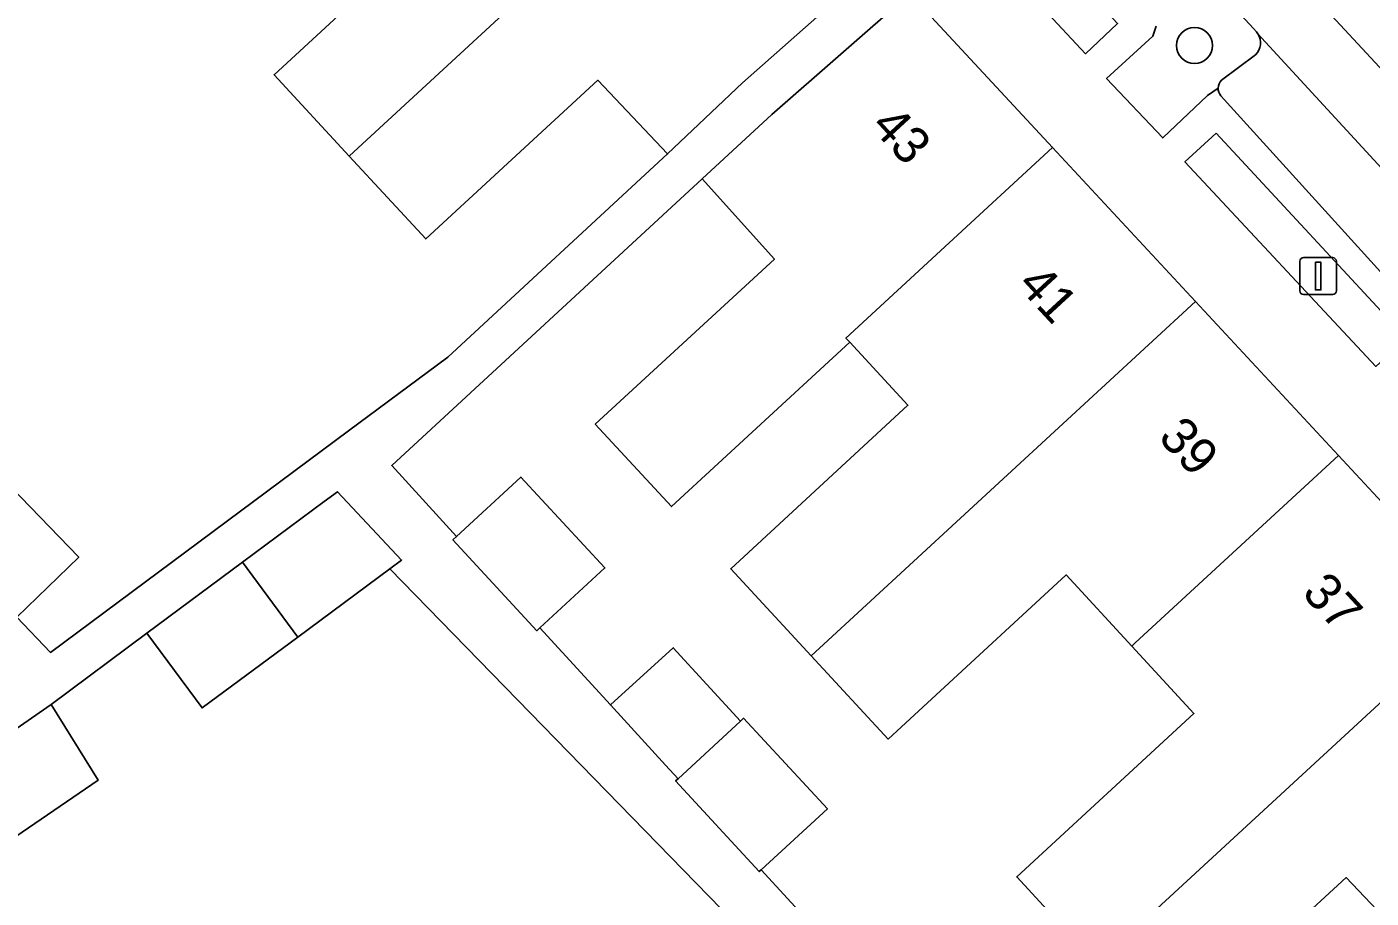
# Model space of a CAD drawing. Extents: x 159716 to 160783, y 383290 to 384031.
# Drawn here: x 160412.95 to 160449.4, y 383595.01 to 383618.65 of the extents above; entities that cross this region are included whole.
import ezdxf

# ---------------------------------------------------------------- set-up
doc = ezdxf.new("R2010")
doc.units = 0
for name, color, linetype in [('IMGEO_Boom', 7, 'Continuous'), ('IMGEO_Erf', 7, 'Continuous'), ('IMGEO_Groenvoorziening', 7, 'Continuous'), ('IMGEO_Lichtmast', 7, 'Continuous'), ('IMGEO_Pand', 7, 'Continuous'), ('IMGEO_Pand_nummerreeks', 7, 'Continuous'), ('IMGEO_Parkeervlak_open', 7, 'Continuous'), ('IMGEO_Rijbaan_lokaal_gesloten', 7, 'Continuous'), ('IMGEO_Rijbaan_lokaal_open', 7, 'Continuous'), ('IMGEO_Voetpad_open', 7, 'Continuous')]:
    doc.layers.add(name, color=color, linetype=linetype)

msp = doc.modelspace()

# ---------------------------------------------------------------- linework, layer by layer
at = {"layer": 'IMGEO_Boom'}
msp.add_circle((160444.613, 383618.147), 0.489, dxfattribs=at)
at = {"layer": 'IMGEO_Erf'}
for points in [[(160412.256, 383606.439), (160414.358, 383604.26), (160412.676, 383602.637), (160413.594, 383601.677), (160421.674, 383607.687), (160424.363, 383609.687), (160430.323, 383615.205), (160428.435, 383617.205), (160423.767, 383612.896), (160421.69, 383615.146), (160419.653, 383617.352), (160424.282, 383621.625), (160422.483, 383623.574), (160420.737, 383625.466), (160416.127, 383621.211), (160414.037, 383623.475), (160412.055, 383625.623), (160416.674, 383629.886), (160414.819, 383631.895), (160413.12, 383633.736), (160408.508, 383629.478)], [(160440.519, 383594.802), (160439.794, 383595.587), (160444.598, 383600.021), (160442.91, 383601.849), (160441.129, 383603.779), (160436.304, 383599.326), (160434.22, 383601.584), (160432.037, 383603.949), (160436.842, 383608.384), (160435.262, 383610.096), (160430.427, 383605.634), (160428.364, 383607.869), (160433.219, 383612.35), (160431.262, 383614.527), (160422.843, 383606.746), (160424.602, 383604.821), (160426.349, 383606.434), (160428.624, 383603.97), (160426.864, 383602.346), (160428.776, 383600.253), (160430.476, 383601.806), (160432.299, 383599.812), (160432.387, 383599.893), (160434.656, 383597.434), (160432.866, 383595.782), (160436.216, 383592.123)], [(160411.784, 383580.396), (160414.301, 383582.347), (160418.229, 383577.282), (160419.676, 383578.404), (160421.151, 383579.547), (160417.211, 383584.628), (160419.701, 383586.558), (160422.209, 383588.503), (160426.134, 383583.438), (160427.591, 383584.567), (160429.122, 383585.755), (160425.189, 383590.828), (160427.622, 383592.715), (160430.084, 383594.625), (160433.988, 383589.59), (160435.593, 383590.804), (160422.791, 383603.945), (160420.296, 383602.093), (160417.704, 383600.17), (160416.206, 383602.202), (160413.613, 383600.264), (160414.882, 383598.21), (160412.127, 383596.328)], [(160450.731, 383593.456), (160448.722, 383595.569), (160443.909, 383591.127)]]:
    msp.add_lwpolyline(points, dxfattribs=at)
at = {"layer": 'IMGEO_Groenvoorziening'}
for points in [[(160437.238, 383624.444), (160436.346, 383623.624), (160441.658, 383617.922), (160442.526, 383618.74)], [(160445.202, 383615.77), (160444.35, 383614.989), (160449.531, 383609.44), (160450.36, 383610.199)]]:
    msp.add_lwpolyline(points, close=True, dxfattribs=at)
for points in [[(160446.333, 383618.467), (160446.294, 383618.52), (160446.214, 383618.606), (160445.753, 383619.101), (160445.392, 383619.488), (160445.286, 383619.599)], [(160443.569, 383618.667), (160443.485, 383618.403), (160442.229, 383617.255), (160443.751, 383615.637), (160444.965, 383616.793), (160445.255, 383616.992)], [(160445.347, 383617.201), (160446.266, 383617.891)]]:
    msp.add_lwpolyline(points, dxfattribs=at)
for centre, radius, start, end in [((160445.937, 383618.221), 0.466, 314.8788, 31.8516), ((160445.566, 383616.98), 0.311, 134.6904, 177.7923)]:
    msp.add_arc(centre, radius, start, end, dxfattribs=at)
at = {"layer": 'IMGEO_Lichtmast'}
for p, q in [((160447.47, 383611.49), (160447.47, 383612.29)), ((160447.47, 383612.29), (160447.47, 383611.49)), ((160447.57, 383612.39), (160448.36, 383612.39)), ((160448.36, 383612.39), (160447.57, 383612.39)), ((160448.46, 383612.29), (160448.46, 383611.49)), ((160448.46, 383611.49), (160448.46, 383612.29)), ((160448.36, 383611.39), (160447.57, 383611.39)), ((160447.57, 383611.39), (160448.36, 383611.39))]:
    msp.add_line(p, q, dxfattribs=at)
msp.add_lwpolyline([(160447.89, 383612.265), (160448.04, 383612.265), (160448.04, 383611.515), (160447.89, 383611.515), (160447.89, 383612.265)], dxfattribs=at)
for centre, start, end in [((160447.57, 383612.29), 90, 180), ((160447.57, 383612.29), 90, 180), ((160448.36, 383612.29), 0, 90), ((160448.36, 383612.29), 360, 90), ((160447.57, 383611.49), 180, 270), ((160447.57, 383611.49), 180, 270), ((160448.36, 383611.49), 270, 0), ((160448.36, 383611.49), 270, 0)]:
    msp.add_arc(centre, 0.1, start, end, dxfattribs=at)
at = {"layer": 'IMGEO_Pand'}
for points in [[(160432.084, 383624.739), (160428.236, 383628.884), (160422.679, 383623.755), (160422.483, 383623.574), (160424.282, 383621.625), (160419.653, 383617.352), (160421.69, 383615.146), (160421.813, 383615.259)], [(160436.079, 383620.435), (160432.084, 383624.739), (160421.813, 383615.259), (160421.69, 383615.146), (160423.767, 383612.896), (160428.435, 383617.205), (160430.323, 383615.205), (160432.354, 383617.13)], [(160440.764, 383615.382), (160436.893, 383619.556), (160433.15, 383616.272), (160431.262, 383614.527), (160433.219, 383612.35), (160428.364, 383607.869), (160430.427, 383605.634), (160435.262, 383610.096), (160435.159, 383610.208)], [(160444.64, 383611.203), (160440.764, 383615.382), (160435.159, 383610.208), (160435.262, 383610.096), (160436.842, 383608.384), (160432.037, 383603.949), (160434.22, 383601.584), (160434.447, 383601.794)], [(160448.515, 383607.023), (160444.64, 383611.203), (160434.447, 383601.794), (160434.22, 383601.584), (160436.304, 383599.326), (160441.129, 383603.779), (160442.91, 383601.849), (160443.002, 383601.934)], [(160452.391, 383602.844), (160448.515, 383607.023), (160443.002, 383601.934), (160442.91, 383601.849), (160444.598, 383600.021), (160439.794, 383595.587), (160440.519, 383594.802), (160441.972, 383593.226)], [(160412.256, 383606.439), (160410.548, 383604.864), (160410.498, 383604.817), (160412.638, 383602.6), (160412.676, 383602.637), (160414.358, 383604.26)], [(160424.602, 383604.821), (160424.504, 383604.731), (160426.778, 383602.267), (160426.864, 383602.346), (160428.624, 383603.97), (160426.349, 383606.434)], [(160421.014, 383605.769), (160418.798, 383604.125), (160420.296, 383602.093), (160422.791, 383603.945), (160423.113, 383604.184), (160421.373, 383606.036)], [(160420.296, 383602.093), (160418.798, 383604.125), (160416.206, 383602.202), (160417.704, 383600.17)], [(160456.328, 383598.598), (160452.391, 383602.844), (160441.972, 383593.226), (160443.909, 383591.127), (160448.722, 383595.569), (160450.731, 383593.456), (160452.802, 383595.359)], [(160430.476, 383601.806), (160428.776, 383600.253), (160430.271, 383598.617), (160430.607, 383598.25), (160432.299, 383599.812)], [(160410.661, 383598.218), (160412.127, 383596.328), (160414.882, 383598.21), (160413.613, 383600.264)], [(160432.299, 383599.812), (160430.607, 383598.25), (160430.542, 383598.19), (160432.811, 383595.731), (160432.866, 383595.782), (160434.656, 383597.434), (160432.387, 383599.893)]]:
    msp.add_lwpolyline(points, close=True, dxfattribs=at)
at = {"layer": 'IMGEO_Parkeervlak_open'}
for points in [[(160459.018, 383604.673), (160446.333, 383618.467)], [(160446.266, 383617.891), (160445.347, 383617.201)], [(160445.327, 383616.78), (160457.086, 383603.81)]]:
    msp.add_lwpolyline(points, dxfattribs=at)
for centre, radius, start, end in [((160445.937, 383618.221), 0.466, 314.8788, 31.8516), ((160445.566, 383616.98), 0.311, 134.6904, 177.7923), ((160445.561, 383616.978), 0.306, 177.3228, 220.1945)]:
    msp.add_arc(centre, radius, start, end, dxfattribs=at)
at = {"layer": 'IMGEO_Rijbaan_lokaal_gesloten'}
msp.add_lwpolyline([(160428.501, 383637.667), (160431.144, 383634.815), (160431.472, 383634.461), (160432.462, 383633.429), (160432.527, 383633.339), (160445.286, 383619.599), (160445.392, 383619.488), (160445.753, 383619.101), (160446.214, 383618.606), (160446.294, 383618.52), (160446.333, 383618.467), (160459.018, 383604.673), (160459.094, 383604.601), (160460.412, 383605.803), (160451.956, 383615.047), (160433.35, 383635.117)], dxfattribs=at)
at = {"layer": 'IMGEO_Rijbaan_lokaal_open'}
msp.add_lwpolyline([(160430.561, 383638.144), (160433.35, 383635.117), (160451.956, 383615.047), (160460.412, 383605.803), (160459.094, 383604.601), (160459.348, 383604.307), (160464.132, 383608.674), (160463.857, 383608.975), (160462.488, 383607.758), (160454.707, 383616.185), (160444.209, 383627.615), (160437.436, 383634.886), (160423.641, 383649.415), (160423.767, 383649.538), (160424.907, 383650.657)], dxfattribs=at)
at = {"layer": 'IMGEO_Voetpad_open'}
for points in [[(160409.048, 383648.938), (160410.515, 383647.343), (160412.772, 383645.544), (160416.693, 383641.32), (160420.54, 383637.175), (160424.389, 383633.03), (160428.236, 383628.884), (160432.084, 383624.739), (160436.079, 383620.435), (160436.893, 383619.556), (160440.764, 383615.382), (160444.64, 383611.203), (160448.515, 383607.023), (160452.391, 383602.844), (160456.328, 383598.598), (160458.067, 383600.195), (160456.072, 383602.378), (160457.215, 383603.452), (160457.285, 383603.724)], [(160436.216, 383592.123), (160432.866, 383595.782), (160432.811, 383595.731), (160430.542, 383598.19), (160430.607, 383598.25), (160430.271, 383598.617), (160428.776, 383600.253), (160426.864, 383602.346), (160426.778, 383602.267), (160424.504, 383604.731), (160424.602, 383604.821), (160422.843, 383606.746), (160431.262, 383614.527), (160433.15, 383616.272), (160436.893, 383619.556), (160436.079, 383620.435), (160432.354, 383617.13), (160430.323, 383615.205), (160424.363, 383609.687), (160421.674, 383607.687), (160413.594, 383601.677), (160412.676, 383602.637)], [(160445.255, 383616.992), (160444.965, 383616.793), (160443.751, 383615.637), (160442.229, 383617.255), (160443.485, 383618.403), (160443.569, 383618.667)], [(160457.086, 383603.81), (160445.327, 383616.78)], [(160410.661, 383598.218), (160413.613, 383600.264), (160416.206, 383602.202), (160418.798, 383604.125), (160421.014, 383605.769), (160421.373, 383606.036), (160423.113, 383604.184), (160422.791, 383603.945), (160435.593, 383590.804)]]:
    msp.add_lwpolyline(points, dxfattribs=at)
for points in [[(160437.238, 383624.444), (160442.526, 383618.74), (160441.658, 383617.922), (160436.346, 383623.624)], [(160445.202, 383615.77), (160450.36, 383610.199), (160449.531, 383609.44), (160444.35, 383614.989)]]:
    msp.add_lwpolyline(points, close=True, dxfattribs=at)
msp.add_arc((160445.561, 383616.978), 0.306, 177.3228, 220.1945, dxfattribs=at)

# ---------------------------------------------------------------- texts
at = {"layer": 'IMGEO_Pand_nummerreeks'}
for s, p in [('43', (160435.802, 383615.935)), ('41', (160439.777, 383611.628)), ('39', (160443.597, 383607.488)), ('37', (160447.495, 383603.265))]:
    msp.add_text(s, height=1, rotation=312.7081, dxfattribs=at).set_placement(p)

doc.saveas('drawing.dxf')
